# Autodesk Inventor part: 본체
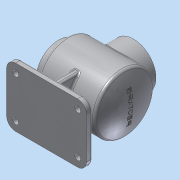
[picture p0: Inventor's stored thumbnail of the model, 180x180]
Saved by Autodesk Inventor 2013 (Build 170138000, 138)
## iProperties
Created: 2016-09
Part Number: 본체
Material: 알루미늄 6061
Document SubType Name: Modeling
Designer: dgall
Density: 2.71 g/cm^3
Mass: 972.437 g
Surface Area: 1283.14 cm^2
Volume: 358.833 cm^3
Author: dgall
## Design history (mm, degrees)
sketch "스케치1"
  geometry: L1 (-61.831, 0)-(60.169, 0); L2 (-61.831, 27)-(-46.831, 27); L3 (-46.831, 27)-(-46.831, 47); L4 (-46.831, 47)-(46.831, 47); L5 (-61.831, 27)-(-61.831, 38); L6 (-61.831, 38)-(-49.831, 38); L7 (-49.831, 38)-(-49.831, 50); L8 (-49.831, 50)-(48.731, 50); A1 r 115 centre (-54.831, 0) between (60.169, 0) and (48.731, 50); A2 r 112 centre (-54.831, 0) between (57.169, 0) and (46.831, 47); 2 further points
  constraints: 16 end point, 4 parallel, 4 point on circle, 3 perpendicular, 2 centre point, 2 horizontal alignment, 2 vertical alignment, 1 coincident, 1 horizontal, 1 midpoint, 1 point on line
  dimensions: "d2" = 115 radius of A1; "d3" = 12 distance of L5.end L6.end; "d4" = 3 distance between parallel lines of L8 L4; "d5" = 110 distance from line of L1.end L7; "d6" = 3 distance of L1.end A2.start; "d7" = 27 distance between parallel lines of L1 L2; "d8" = 38 distance between parallel lines of L1 L6; "d9" = 50 distance between parallel lines of L1 L8; "d10" = 15 distance of L2.start L2.end
revolve "회전1" sketch "스케치1" stored, may be unused: angle "d11" = 90 deg
node "작업 평면2"
sketch "스케치2"
  geometry: L1 (67.5, -50)-(-67.5, -50); L2 (-67.5, -50)-(-67.5, 50); L3 (-67.5, 50)-(67.5, 50); L4 (67.5, 50)-(67.5, -50); L5 (-48.731, 50)-(-48.731, -50) reference; L6 (49.831, 50)-(49.831, -50) reference; L7 (49.831, -50)-(-48.731, -50) reference; A1 r 115 centre (54.831, 0) between (-48.731, 50) and (-48.731, -50) reference; 1 further point
  constraints: 8 end point, 2 parallel, 1 horizontal, 1 perpendicular
  dimensions: "d13" = 135 distance of L1.start L1.end; "d15" = 100 distance of L1.end L2.end; "d95" = 67.5 distance from line of L4 point (0, 0); "d96" = 50 distance from line of L3 point (0, 0)
extrude "돌출1" join sketch "스케치2" distance "d16" = 10; taper "d17" = 0 deg
node "작업 평면3"
sketch "스케치3"
  geometry: L1 (0, 0)-(0, 10) reference; L2 (0, 10)-(100, 10) reference; L3 (100, 10)-(100, 0) reference; L4 (100, 0)-(0, 0) reference; L5 (90, 10)-(90, 52); L6 (10, 10)-(10, 52); C1 r 47 at (50, 82) reference; A1 r 50 centre (50, 82) between (90, 52) and (10, 52) reference; 1 further point
  constraints: 4 end point, 2 point on circle, 2 point on line, 1 parallel, 1 perpendicular
  dimensions: "d19" = 80 distance between parallel lines of L5 L6; "d20" = 40 distance from line of point (50, 82) L6
extrude "돌출2" join sketch "스케치3" stored distance "d21" = 10; taper "d22" = 0 deg
feature "리브1" dims "d30" = 1, "d31" = 10, "d32" = 0, "d33" = 0, "d34" = 1, "d35" = 1
feature "리브2" dims "d36" = 1, "d37" = 10, "d38" = 0, "d39" = 0, "d40" = 1, "d41" = 1
node "작업 평면4"
sketch "스케치5"
  geometry: L1 (49.831, 50)-(49.831, -50) reference; C1 r 38 at (-0.169, 0); 1 further point
  constraints: 1 centre point, 1 horizontal alignment
  dimensions: "d100" = 76 diameter of C1; "d101" = 50 distance from line of L1 C1.centre
extrude "돌출3" join sketch "스케치5" stored distance "d44" = 10; taper "d45" = 0 deg
sketch "스케치11"
  geometry: C1 r 38 at (0, 0) reference; C2 r 27 at (0, 0); 1 further point
  constraints: 1 centre point, 1 concentric
  dimensions: "d122" = 54 diameter of C2
extrude "돌출5" cut sketch "스케치11" stored distance "d105" = 10; taper "d106" = 0 deg
sketch "스케치12"
  geometry: C1 r 27 at (0, 0) reference; 1 further point
  constraints: 1 vertical alignment
  dimensions: "d123" = 32.5 distance of C1.centre point (0, 32.5)
hole "구멍4" sketch "스케치12" at (0, 32.5) diameter "d108" = 3.242; stored, may be unused: countersink angle "d112" = 90 deg, drill point angle "d114" = 118 deg; dims "d109" = 8, "d110" = 4, "d111" = 2, "d113" = 10
fillet "모깎기8" dims "d121" = 3
sketch "스케치8"
  geometry: C1 r 38 at (0, 0) reference; 1 further point
  constraints: 1 vertical alignment
  dimensions: "d61" = 32.5 distance of C1.centre point (0, 32.5)
hole "구멍2" sketch "스케치8" at (0, 32.5) diameter "d62" = 3.242; stored, may be unused: countersink angle "d66" = 90 deg, drill point angle "d68" = 118 deg; dims "d63" = 8, "d64" = 4, "d65" = 2, "d67" = 10
fillet "모깎기1" dims "d72" = 5
fillet "모깎기2" dims "d73" = 2
fillet "모깎기3" dims "d74" = 3
fillet "모깎기4" dims "d75" = 3
fillet "모깎기5" dims "d76" = 15
fillet "모깎기6" dims "d77" = 3
sketch "스케치9"
  geometry: L1 (-36.726, -8)-(-8, -8) reference; L2 (-8, -8)-(-8, -37) reference; L3 (-2, -43)-(2, -43) reference; L4 (8, -37)-(8, -8) reference; L5 (8, -8)-(36.726, -8) reference; L6 (42.749, -2)-(42.749, 2) reference; L7 (36.726, 8)-(8, 8) reference; L8 (8, 8)-(8, 37) reference; L9 (2, 43)-(-2, 43) reference; L10 (-8, 37)-(-8, 8) reference; L11 (-8, 8)-(-36.726, 8) reference; L12 (-42.749, 2)-(-42.749, -2) reference; L13 (-52.5, -47)-(52.5, -47) reference; L14 (64.5, -35)-(64.5, 35) reference; L15 (52.5, 47)-(-52.5, 47) reference; L16 (-64.5, 35)-(-64.5, -35) reference; A1 r 6 centre (-2, -37) between (-8, -37) and (-2, -43) reference; A2 r 6 centre (2, -37) between (2, -43) and (8, -37) reference; A3 r 6 centre (2, 37) between (8, 37) and (2, 43) reference; A4 r 6 centre (-2, 37) between (-2, 43) and (-8, 37) reference; A5 r 15 centre (-52.5, 35) between (-52.5, 50) and (-67.5, 35) reference; A6 r 12 centre (52.5, -35) between (52.5, -47) and (64.5, -35) reference; A7 r 12 centre (52.5, 35) between (64.5, 35) and (52.5, 47) reference; A8 r 12 centre (-52.5, 35) between (-52.5, 47) and (-64.5, 35) reference; A9 r 12 centre (-52.5, -35) between (-64.5, -35) and (-52.5, -47) reference; 5 further points
  constraints: 1 coincident, 4 other
hole "구멍3" sketch "스케치9" diameter "d81" = 10; stored, may be unused: countersink angle "d85" = 90 deg, drill point angle "d87" = 118 deg; dims "d82" = 8, "d83" = 4, "d84" = 2, "d86" = 10
node "작업 평면5"
sketch "스케치10"
  geometry: C1 r 50 at (0, 0) reference; C2 r 47.045 at (0, 0) reference; 2 further points
  constraints: 1 coincident, 1 other
feature "엠보싱1" sketch "스케치10" dims "d89" = 0.5, "d90" = 0
chamfer "모따기1" distance "d91" = 1; stored, may be unused: second distance "d92" = 2, angle "d93" = 45 deg
fillet "모깎기7" dims "d94" = 3
chamfer "모따기3" distance "d124" = 1; stored, may be unused: second distance "d125" = 2, angle "d126" = 45 deg
node "솔리드1"
sketch "스케치4"
  geometry: L1 (46.831, 47)-(-46.831, 47) reference; L2 (-46.831, 47)-(-46.831, 27) reference; L3 (-46.831, 27)-(-61.831, 27) reference; L4 (-61.831, 27)-(-61.831, 38) reference; L5 (-61.831, 38)-(-49.831, 38) reference; L6 (-49.831, 38)-(-49.831, 50) reference; L7 (-49.831, 50)-(48.731, 50) reference; L8 (48.731, -50)-(5, -50) reference; L9 (5, -50)-(5, -72) reference; L10 (5, -72)-(67.5, -72) reference; L11 (67.5, -72)-(67.5, -82) reference; L12 (67.5, -82)-(-67.5, -82) reference; L13 (-67.5, -82)-(-67.5, -72) reference; L14 (-67.5, -72)-(-5, -72) reference; L15 (-5, -72)-(-5, -50) reference; L16 (-5, -50)-(-49.831, -50) reference; L17 (-49.831, -50)-(-49.831, -38) reference; L18 (-49.831, -38)-(-61.831, -38) reference; L19 (-61.831, -38)-(-61.831, -27) reference; L20 (-61.831, -27)-(-46.831, -27) reference; L21 (-46.831, -27)-(-46.831, -47) reference; L22 (-46.831, -47)-(46.831, -47) reference; L23 (-40, -72)-(-38.075, -50); L24 (40, -72)-(38.077, -50.023); L25 (46.831, 47)-(-46.831, 47) reference; L26 (-46.831, 47)-(-46.831, 27) reference; L27 (-46.831, 27)-(-61.831, 27) reference; L28 (-61.831, 27)-(-61.831, 38) reference; L29 (-61.831, 38)-(-49.831, 38) reference; L30 (-49.831, 38)-(-49.831, 50) reference; L31 (-49.831, 50)-(48.731, 50) reference; L32 (48.731, -50)-(5, -50) reference; L33 (5, -50)-(5, -72) reference; L34 (5, -72)-(67.5, -72) reference; L35 (67.5, -72)-(67.5, -82) reference; L36 (67.5, -82)-(-67.5, -82) reference; L37 (-67.5, -82)-(-67.5, -72) reference; L38 (-67.5, -72)-(-5, -72) reference; L39 (-5, -72)-(-5, -50) reference; L40 (-5, -50)-(-49.831, -50) reference; L41 (-49.831, -50)-(-49.831, -38) reference; L42 (-49.831, -38)-(-61.831, -38) reference; L43 (-61.831, -38)-(-61.831, -27) reference; L44 (-61.831, -27)-(-46.831, -27) reference; L45 (-46.831, -27)-(-46.831, -47) reference; L46 (-46.831, -47)-(46.831, -47) reference; A1 r 112 centre (-54.831, 0) between (46.831, -47) and (46.831, 47) reference; A2 r 115 centre (-54.831, 0) between (48.731, -50) and (48.731, 50) reference; A3 r 112 centre (-54.831, 0) between (46.831, -47) and (46.831, 47) reference; A4 r 115 centre (-54.831, 0) between (48.731, -50) and (48.731, 50) reference; 1 further point
  constraints: 4 end point, 3 point on line
  dimensions: "d24" = 95 deg angle of L14 L23; "d97" = 40 horizontal distance of point (0, 0) L23.start; "d98" = 40 horizontal distance of L24.start point (0, 0); "d99" = 95 deg angle of L10 L24
pattern_circular "원형 패턴3" dims angle "d116" = 360 deg
pattern_circular "원형 패턴2" dims angle "d70" = 360 deg
node "투영된 루프1"
node "투영된 루프2"
node "절단 모서리 투영1"
node "절단 모서리 투영2"
node "절단 모서리 투영3"
node "절단 모서리 투영4"
other parameters: "d12" = -82, "d18" = -67.5, "d42" = -147
